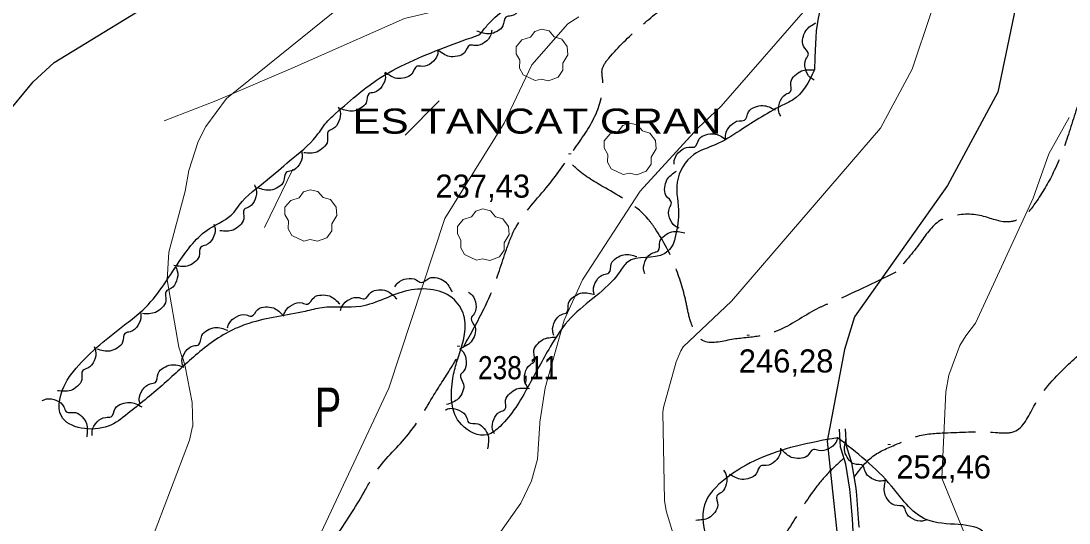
# Model space of a CAD drawing. Extents: x 480269 to 484877, y 4383588 to 4386804.
# Drawn here: x 483238.1 to 483634.3, y 4385540.7 to 4385730.7 of the extents above; entities that cross this region are included whole.
import ezdxf
from ezdxf.enums import TextEntityAlignment as Align

# ---------------------------------------------------------------- set-up
doc = ezdxf.new("R2010")
doc.units = 0
doc.header["$LTSCALE"] = 3.8
doc.linetypes.add('LONG_DASHED', pattern=[7.5, 6, -1.5])
doc.linetypes.add('MEDIUM_DASHED', pattern=[4.5, 3, -1.5])
for name, color, linetype, lineweight in [('27', 7, 'Continuous', 25), ('29', 7, 'Continuous', 13), ('38', 7, 'Continuous', 25), ('51', 7, 'Continuous', 13), ('7', 7, 'Continuous', 13), ('8', 7, 'Continuous', 25), ('9', 7, 'Continuous', 13)]:
    doc.layers.add(name, color=color, linetype=linetype, lineweight=lineweight)
doc.layers.add('31', color=7, linetype='Continuous')
doc.layers.add('5', color=7, linetype='Continuous')

msp = doc.modelspace()

# ---------------------------------------------------------------- linework, layer by layer
at = {"layer": '27'}
for points in [[(483411.62, 4385725.63), (483414.38, 4385729.12), (483445.75, 4385743.87), (483460.12, 4385746.17), (483467.72, 4385750.51), (483481.35, 4385756.24), (483494.17, 4385762.47), (483510.38, 4385771.95), (483513.98, 4385779.76), (483520.25, 4385796.38), (483532.76, 4385804.22), (483539.43, 4385807.59), (483542.56, 4385816.61), (483548.02, 4385830.65), (483556.04, 4385838.51), (483560.7, 4385820.62), (483568.17, 4385814.97), (483571.22, 4385796.89), (483575.67, 4385789), (483572.83, 4385770.57), (483560.28, 4385760.77), (483555.71, 4385755.51), (483541.6, 4385738.48), (483538.33, 4385719.63), (483538.1, 4385712.19)], [(483427.62, 4385740.1), (483427.84, 4385738.34), (483426.43, 4385734.81), (483423.43, 4385732.66), (483421.43, 4385732.22), (483420.27, 4385728.86), (483418.1, 4385726.81), (483415.23, 4385725.85), (483410.38, 4385726.92)], [(483537.98, 4385708.39), (483536.48, 4385709.34), (483534.64, 4385712.65), (483534.87, 4385716.34), (483535.79, 4385718.17), (483533.92, 4385721.19), (483533.71, 4385724.17), (483534.78, 4385727), (483538.66, 4385730.08)], [(483538.1, 4385712.19), (483529.76, 4385700.75), (483526.84, 4385699.24), (483509.81, 4385689.19), (483500.55, 4385683.88), (483492.53, 4385680.19), (483486.19, 4385669.67), (483486.71, 4385657.76), (483485.29, 4385648.37), (483485.16, 4385647.8), (483481.49, 4385642.76), (483467.34, 4385639.44), (483464.26, 4385635.56), (483446.1, 4385618.52), (483438.16, 4385607.39), (483429.82, 4385592.36), (483419.2, 4385577.29), (483414.42, 4385574.14), (483404.58, 4385577.96), (483401.38, 4385595.6), (483402.78, 4385601.5), (483405.77, 4385618.38), (483401.92, 4385625.2), (483384.54, 4385628.72), (483366.51, 4385622.71), (483351.92, 4385622.2), (483345.46, 4385620.82), (483324.28, 4385616.29), (483317.38, 4385613.48), (483303.26, 4385603.51), (483291.44, 4385592.81), (483278.46, 4385582.12), (483271.01, 4385577.36), (483253.33, 4385581.16), (483255.15, 4385594.09), (483258.92, 4385599.33), (483277.81, 4385616.18), (483284.13, 4385621.33), (483297.88, 4385639.66), (483309.29, 4385652.14), (483318.55, 4385658.26), (483320.55, 4385660.97), (483331.14, 4385670.55), (483339.59, 4385677.76), (483349.83, 4385687.26), (483354.13, 4385693), (483355.92, 4385694.7), (483364.88, 4385702.55), (483372.51, 4385708.31), (483398.18, 4385720.66), (483411.62, 4385725.63)], [(483416.08, 4385727.28), (483415.76, 4385725.53), (483413.38, 4385722.58), (483409.88, 4385721.4), (483407.83, 4385721.57), (483405.74, 4385718.7), (483403.06, 4385717.39), (483400.04, 4385717.32), (483395.72, 4385719.76)], [(483395.77, 4385719.65), (483395.53, 4385717.89), (483393.28, 4385714.84), (483389.83, 4385713.52), (483387.78, 4385713.6), (483385.81, 4385710.64), (483383.19, 4385709.22), (483380.17, 4385709.01), (483375.76, 4385711.27)], [(483375.57, 4385711.26), (483375.84, 4385709.51), (483374.54, 4385705.94), (483371.61, 4385703.7), (483369.62, 4385703.2), (483368.57, 4385699.8), (483366.45, 4385697.69), (483363.62, 4385696.64), (483358.74, 4385697.56)], [(483525.32, 4385694.66), (483524.62, 4385696.29), (483524.97, 4385700.07), (483527.23, 4385702.99), (483529.03, 4385703.98), (483529.18, 4385707.53), (483530.69, 4385710.11), (483533.17, 4385711.84), (483538.11, 4385712.19)], [(483358.03, 4385698.17), (483358.72, 4385696.54), (483358.31, 4385692.76), (483356, 4385689.88), (483354.19, 4385688.92), (483353.99, 4385685.37), (483352.44, 4385682.81), (483349.94, 4385681.12), (483344.99, 4385680.83)], [(483504.52, 4385686.07), (483504.51, 4385687.85), (483506.34, 4385691.17), (483509.57, 4385692.95), (483511.62, 4385693.14), (483513.17, 4385696.34), (483515.58, 4385698.11), (483518.54, 4385698.72), (483523.22, 4385697.08)], [(483485.02, 4385676.58), (483485.17, 4385678.35), (483487.27, 4385681.51), (483490.64, 4385683.01), (483492.7, 4385683.03), (483494.51, 4385686.09), (483497.06, 4385687.64), (483500.06, 4385688), (483504.59, 4385685.97)], [(483344.1, 4385681.61), (483344.41, 4385679.86), (483343.19, 4385676.27), (483340.31, 4385673.96), (483338.34, 4385673.41), (483337.36, 4385669.99), (483335.3, 4385667.84), (483332.49, 4385666.73), (483327.59, 4385667.53)], [(483603.65, 4385366.99), (483624.2, 4385382.47), (483632.03, 4385398.91), (483636.72, 4385422.41), (483645.34, 4385439.65), (483660.21, 4385444.35), (483671.96, 4385455.31), (483662.56, 4385467.06), (483659.43, 4385476.46), (483674.31, 4385492.91), (483694.66, 4385499.96), (483704.06, 4385490.56), (483711.11, 4385468.63), (483722.85, 4385451.4), (483736.16, 4385456.1), (483742.42, 4385467.85), (483748.69, 4385484.3), (483759.65, 4385490.56), (483776.88, 4385484.3), (483802.71, 4385469.41), (483826.99, 4385463.15), (483860.65, 4385463.15), (483873.96, 4385476.46), (483902.15, 4385486.65), (483911.55, 4385506.23), (483932.69, 4385513.28), (483942.86, 4385514.85), (483932.69, 4385531.3), (483915.46, 4385547.75), (483903.72, 4385547.75), (483886.49, 4385539.13), (483871.61, 4385529.73), (483863.78, 4385533.65), (483865.35, 4385544.61), (483871.61, 4385560.28), (483873.96, 4385572.03), (483874.75, 4385588.48), (483884.93, 4385596.31), (483910.76, 4385592.4), (483924.07, 4385597.1), (483936.6, 4385618.25), (483939.73, 4385664.46), (483945.7, 4385679.85)], [(483486.97, 4385652.28), (483485.4, 4385653.1), (483483.31, 4385656.27), (483483.24, 4385659.96), (483484.02, 4385661.86), (483481.92, 4385664.72), (483481.48, 4385667.67), (483482.32, 4385670.58), (483485.96, 4385673.95)], [(483326.32, 4385668.68), (483327.01, 4385667.04), (483326.61, 4385663.27), (483324.31, 4385660.38), (483322.5, 4385659.42), (483322.3, 4385655.87), (483320.76, 4385653.31), (483318.26, 4385651.61), (483313.31, 4385651.32)], [(483310.96, 4385653.88), (483311.44, 4385652.17), (483310.58, 4385648.47), (483307.94, 4385645.89), (483306.03, 4385645.15), (483305.39, 4385641.65), (483303.55, 4385639.31), (483300.86, 4385637.92), (483295.91, 4385638.24)], [(483473.96, 4385635.02), (483473.49, 4385636.74), (483474.37, 4385640.42), (483477.03, 4385642.99), (483478.95, 4385643.72), (483479.6, 4385647.21), (483481.46, 4385649.55), (483484.15, 4385650.92), (483489.1, 4385650.57)], [(483454.85, 4385627.06), (483454.49, 4385628.8), (483455.61, 4385632.43), (483458.42, 4385634.82), (483460.39, 4385635.42), (483461.26, 4385638.86), (483463.27, 4385641.08), (483466.05, 4385642.27), (483470.96, 4385641.6)], [(483296.42, 4385637.8), (483297.16, 4385636.19), (483296.89, 4385632.4), (483294.69, 4385629.44), (483292.92, 4385628.41), (483292.85, 4385624.85), (483291.4, 4385622.24), (483288.96, 4385620.45), (483284.02, 4385619.99)], [(483379.43, 4385630.1), (483380.46, 4385631.54), (483383.88, 4385633.19), (483387.54, 4385632.75), (483389.32, 4385631.72), (483392.44, 4385633.43), (483395.43, 4385633.46), (483398.19, 4385632.24), (483401.04, 4385628.18)], [(483337.4, 4385619.1), (483337.96, 4385620.78), (483340.74, 4385623.36), (483344.38, 4385624.02), (483346.38, 4385623.56), (483348.86, 4385626.11), (483351.7, 4385627.02), (483354.7, 4385626.66), (483358.62, 4385623.62)], [(483358.91, 4385621.14), (483359.48, 4385622.82), (483362.28, 4385625.38), (483365.92, 4385626.02), (483367.91, 4385625.54), (483370.41, 4385628.07), (483373.26, 4385628.97), (483376.26, 4385628.59), (483380.16, 4385625.53)], [(483407.24, 4385628.13), (483408.62, 4385627.02), (483410.05, 4385623.51), (483409.39, 4385619.87), (483408.26, 4385618.16), (483409.76, 4385614.94), (483409.62, 4385611.96), (483408.22, 4385609.28), (483404, 4385606.68)], [(483439.58, 4385611.67), (483439.1, 4385613.38), (483439.94, 4385617.08), (483442.56, 4385619.68), (483444.47, 4385620.42), (483445.09, 4385623.92), (483446.92, 4385626.28), (483449.6, 4385627.68), (483454.55, 4385627.38)], [(483316.19, 4385614.56), (483316.75, 4385616.24), (483319.53, 4385618.82), (483323.16, 4385619.49), (483325.17, 4385619.03), (483327.65, 4385621.57), (483330.49, 4385622.49), (483333.49, 4385622.13), (483337.41, 4385619.09)], [(483283.12, 4385620.81), (483283.44, 4385619.06), (483282.26, 4385615.46), (483279.41, 4385613.12), (483277.44, 4385612.55), (483276.5, 4385609.12), (483274.46, 4385606.94), (483271.66, 4385605.8), (483266.75, 4385606.55)], [(483299.18, 4385600.32), (483298.94, 4385602.08), (483300.32, 4385605.61), (483303.29, 4385607.8), (483305.29, 4385608.26), (483306.41, 4385611.64), (483308.56, 4385613.7), (483311.42, 4385614.69), (483316.28, 4385613.68)], [(483429.63, 4385592.15), (483428.74, 4385593.68), (483428.64, 4385597.48), (483430.54, 4385600.64), (483432.2, 4385601.84), (483431.93, 4385605.39), (483433.12, 4385608.13), (483435.37, 4385610.14), (483440.24, 4385611.08)], [(483265.69, 4385607.57), (483266.3, 4385605.9), (483265.73, 4385602.15), (483263.3, 4385599.37), (483261.45, 4385598.49), (483261.09, 4385594.95), (483259.44, 4385592.47), (483256.87, 4385590.88), (483251.91, 4385590.81)], [(483403.99, 4385606.68), (483405.27, 4385605.46), (483406.41, 4385601.84), (483405.46, 4385598.27), (483404.19, 4385596.66), (483405.43, 4385593.33), (483405.04, 4385590.37), (483403.43, 4385587.81), (483399.01, 4385585.56)], [(483283.06, 4385585.79), (483282.77, 4385587.54), (483284.02, 4385591.12), (483286.92, 4385593.41), (483288.91, 4385593.93), (483289.91, 4385597.35), (483291.99, 4385599.48), (483294.81, 4385600.57), (483299.7, 4385599.72)], [(483417.05, 4385574.52), (483416.39, 4385576.17), (483416.86, 4385579.94), (483419.22, 4385582.78), (483421.05, 4385583.72), (483421.31, 4385587.26), (483422.9, 4385589.79), (483425.43, 4385591.45), (483430.38, 4385591.64)], [(483246.07, 4385587.04), (483247.73, 4385587.67), (483251.49, 4385587.12), (483254.28, 4385584.71), (483255.18, 4385582.86), (483258.72, 4385582.53), (483261.22, 4385580.89), (483262.82, 4385578.33), (483262.92, 4385573.37)], [(483264.98, 4385573.89), (483265, 4385575.67), (483266.86, 4385578.97), (483270.11, 4385580.72), (483272.16, 4385580.89), (483273.74, 4385584.08), (483276.16, 4385585.82), (483279.13, 4385586.4), (483283.8, 4385584.71)], [(483398.51, 4385583.59), (483400.21, 4385584.1), (483403.92, 4385583.31), (483406.55, 4385580.72), (483407.32, 4385578.81), (483410.83, 4385578.25), (483413.21, 4385576.45), (483414.65, 4385573.78), (483414.42, 4385568.83)], [(483546.8, 4385573.01), (483530.82, 4385569.72), (483504.5, 4385557.5), (483496.51, 4385547.62), (483497.92, 4385533.98), (483509.2, 4385521.29), (483517.19, 4385516.59), (483525.65, 4385519.41), (483535.05, 4385523.64), (483540.22, 4385520.82), (483543.04, 4385508.12), (483538.34, 4385488.84), (483519.07, 4385474.27), (483501.68, 4385462.04), (483485.7, 4385448.88), (483481.94, 4385449.35), (483483.82, 4385456.4), (483491.34, 4385463.45), (483493.69, 4385472.39), (483482.41, 4385488.84), (483469.72, 4385479.44), (483457.5, 4385473.8), (483447.16, 4385476.15), (483435.41, 4385469.57), (483432.12, 4385452.64), (483431.65, 4385426.31), (483427.89, 4385415.96), (483416.61, 4385410.32), (483407.68, 4385404.21), (483394.53, 4385402.8), (483381.37, 4385399.03), (483373.85, 4385390.57), (483366.33, 4385379.29), (483360.69, 4385372.7), (483348.47, 4385369.41), (483324.97, 4385367.06), (483298.65, 4385356.72), (483277.03, 4385345.43), (483258.23, 4385329.91), (483253.06, 4385332.26), (483259.17, 4385339.32), (483268.1, 4385347.78), (483265.28, 4385357.19), (483251.65, 4385366.59), (483243.66, 4385376.46), (483231.44, 4385369.41), (483229.09, 4385383.05), (483230.97, 4385390.1)], [(483546.8, 4385573.01), (483546.23, 4385571.33), (483543.43, 4385568.77), (483539.79, 4385568.14), (483537.79, 4385568.61), (483535.29, 4385566.09), (483532.44, 4385565.19), (483529.44, 4385565.58), (483525.54, 4385568.64)], [(483677.76, 4385562.31), (483673.47, 4385559.38), (483664.07, 4385546.21), (483641.98, 4385535.4), (483622.71, 4385528.34), (483605.79, 4385512.83), (483595.92, 4385502.95), (483584.17, 4385505.77), (483587.93, 4385512.36), (483602.97, 4385527.4), (483602.97, 4385535.87), (483581.82, 4385541.51), (483567.25, 4385554.67), (483546.8, 4385573.01)], [(483565.04, 4385557), (483563.31, 4385556.59), (483559.66, 4385557.62), (483557.2, 4385560.37), (483556.54, 4385562.32), (483553.08, 4385563.1), (483550.81, 4385565.05), (483549.55, 4385567.8), (483550.09, 4385572.73)], [(483525.28, 4385569.1), (483525.18, 4385567.33), (483523.18, 4385564.11), (483519.85, 4385562.51), (483517.8, 4385562.42), (483516.08, 4385559.31), (483513.58, 4385557.68), (483510.59, 4385557.23), (483506.01, 4385559.13)], [(483503.69, 4385560.77), (483504.6, 4385559.24), (483504.74, 4385555.45), (483502.88, 4385552.27), (483501.22, 4385551.05), (483501.53, 4385547.51), (483500.37, 4385544.76), (483498.14, 4385542.72), (483493.28, 4385541.73)], [(483580.64, 4385541.92), (483578.94, 4385541.43), (483575.24, 4385542.28), (483572.64, 4385544.9), (483571.89, 4385546.81), (483568.39, 4385547.43), (483566.03, 4385549.26), (483564.64, 4385551.94), (483564.93, 4385556.89)]]:
    msp.add_spline(points, degree=3, dxfattribs=at)
at = {"layer": '29'}
for points in [[(483432.49, 4385708.2), (483427.95, 4385710.32), (483426.54, 4385712.86), (483426.64, 4385715.84), (483425.27, 4385718.25), (483425.31, 4385721), (483427.47, 4385723.6), (483430.66, 4385724.6), (483432.31, 4385726.79), (483434.88, 4385727.62), (483437.74, 4385726.97), (483439.69, 4385724.7), (483442.5, 4385723.88), (483444.63, 4385721.03), (483444.87, 4385717.9), (483442.99, 4385714.75), (483442.99, 4385712.07), (483441.17, 4385709.46), (483437.55, 4385708.12), (483434.78, 4385708.75)], [(483465.81, 4385672.62), (483461.27, 4385674.74), (483459.86, 4385677.28), (483459.96, 4385680.26), (483458.59, 4385682.67), (483458.63, 4385685.42), (483460.79, 4385688.02), (483463.98, 4385689.02), (483465.63, 4385691.21), (483468.2, 4385692.04), (483471.06, 4385691.39), (483473.01, 4385689.12), (483475.82, 4385688.3), (483477.95, 4385685.45), (483478.19, 4385682.32), (483476.31, 4385679.17), (483476.31, 4385676.49), (483474.49, 4385673.88), (483470.87, 4385672.54), (483468.1, 4385673.17)], [(483345.07, 4385647.43), (483340.53, 4385649.55), (483339.12, 4385652.09), (483339.22, 4385655.07), (483337.85, 4385657.48), (483337.89, 4385660.23), (483340.05, 4385662.83), (483343.24, 4385663.83), (483344.89, 4385666.02), (483347.46, 4385666.85), (483350.32, 4385666.2), (483352.27, 4385663.93), (483355.08, 4385663.11), (483357.21, 4385660.26), (483357.45, 4385657.13), (483355.57, 4385653.98), (483355.57, 4385651.3), (483353.75, 4385648.69), (483350.13, 4385647.35), (483347.36, 4385647.98)], [(483410.28, 4385640.17), (483405.74, 4385642.29), (483404.33, 4385644.83), (483404.43, 4385647.81), (483403.06, 4385650.22), (483403.1, 4385652.97), (483405.26, 4385655.57), (483408.45, 4385656.57), (483410.1, 4385658.76), (483412.67, 4385659.59), (483415.53, 4385658.94), (483417.48, 4385656.67), (483420.29, 4385655.85), (483422.42, 4385653), (483422.66, 4385649.87), (483420.78, 4385646.72), (483420.78, 4385644.04), (483418.96, 4385641.43), (483415.34, 4385640.09), (483412.57, 4385640.72)]]:
    msp.add_lwpolyline(points, close=True, dxfattribs=at)
at = {"layer": '38'}
msp.add_lwpolyline([(483552.77, 4385537.55), (483552.47, 4385542.27), (483551.73, 4385551.05), (483551.49, 4385553.6), (483549.9, 4385562.95), (483548.28, 4385568.32), (483547.92, 4385569.42), (483547.55, 4385576.23)], dxfattribs=at)
at = {"layer": '38', "linetype": 'MEDIUM_DASHED'}
msp.add_lwpolyline([(483561.28, 4385439.02), (483565.89, 4385449.17), (483567.14, 4385456.9), (483567.2, 4385464.1), (483567.16, 4385466.2), (483568.62, 4385474.3), (483569.47, 4385477.73), (483570.95, 4385483.54), (483570.94, 4385486.99), (483569.15, 4385493.62), (483565.29, 4385501.69), (483560.98, 4385507.84), (483559.66, 4385511.97), (483558.57, 4385516.81), (483557, 4385522.51), (483555.08, 4385539.19), (483554.99, 4385539.22), (483554.78, 4385542.44), (483554.04, 4385551.25), (483553.79, 4385553.9), (483552.16, 4385563.48), (483550.49, 4385569.01), (483550.22, 4385569.85), (483549.87, 4385576.35)], dxfattribs=at)
at = {"layer": '38', "linetype": 'LONG_DASHED'}
for points in [[(483222.84, 4385328.78), (483233.49, 4385331.65), (483248.44, 4385336.61), (483252.54, 4385340.94), (483258.88, 4385354.18), (483261.76, 4385364.09), (483264.07, 4385370.4), (483271.55, 4385381.16), (483280.42, 4385394.23), (483287.47, 4385408.23), (483295.91, 4385425.29), (483304.52, 4385439.96), (483308.91, 4385446.59), (483318.63, 4385460.51), (483325.16, 4385473.38), (483329.03, 4385484.99), (483336.9, 4385500.43), (483342.08, 4385509.3), (483351.29, 4385526.25), (483356.88, 4385535.07), (483367.82, 4385552.46), (483372.61, 4385560.56), (483384.55, 4385574.31), (483394.22, 4385589.19), (483401.11, 4385600.15), (483408.96, 4385613.82), (483416.11, 4385628.46), (483421.62, 4385644.25), (483425.26, 4385652.82), (483437.44, 4385668.5), (483447.61, 4385682.66), (483455.49, 4385695.61), (483457.94, 4385709.1), (483457.8, 4385712.22), (483460.32, 4385716.64), (483471.95, 4385728.32), (483483.41, 4385737.85), (483491.91, 4385744.84), (483502.88, 4385754.26), (483511.53, 4385762), (483517.86, 4385770.14), (483520.82, 4385773.68), (483521.2, 4385789.84), (483522.3, 4385808.2), (483521.83, 4385825.17), (483522.61, 4385837.11), (483524.33, 4385844.04), (483529.61, 4385862.88), (483530.12, 4385879.57), (483529.5, 4385895.4), (483531.44, 4385911.89), (483533.11, 4385922.24), (483534.94, 4385934.41), (483535.75, 4385947.11), (483535.49, 4385954.95), (483538.08, 4385971.48), (483542.8, 4385983), (483551.34, 4385997.49), (483555.36, 4386004.16), (483555.47, 4386004.25)], [(483804.51, 4385920.94), (483788.05, 4385895.48), (483779.36, 4385885.64), (483767.14, 4385873.56), (483740.9, 4385842.33), (483734.1, 4385833.64), (483725.43, 4385817.26), (483714.11, 4385791.82), (483710.8, 4385781.06), (483710.16, 4385770.49), (483707.13, 4385759.38), (483703.28, 4385752.81), (483694.46, 4385748.4), (483680.9, 4385745.07), (483669.5, 4385743.91), (483655.77, 4385731.07), (483647.05, 4385718.23), (483639.81, 4385704.57), (483634.39, 4385688.76), (483628.75, 4385674.1), (483622.15, 4385662.64), (483615.35, 4385655.69), (483611.37, 4385654.69), (483601.39, 4385656.95), (483588.98, 4385656.57), (483586.28, 4385655.56), (483578.11, 4385646.87), (483568.89, 4385635.65)], [(483269.19, 4385377.79), (483265.83, 4385379.76), (483259.03, 4385384.12), (483248.33, 4385390.08), (483241.93, 4385401.56), (483240.31, 4385411.32), (483239.53, 4385423.1), (483237.61, 4385429.2), (483228.77, 4385444.16), (483215.59, 4385471.64), (483211.39, 4385484.05), (483206.78, 4385496.53), (483203.95, 4385506.6), (483198.79, 4385527.78), (483197.64, 4385533.81), (483194.47, 4385554.66), (483187.12, 4385575.33), (483180.81, 4385599.81), (483178.92, 4385612.27), (483174.66, 4385634.07), (483172.09, 4385649.52), (483170.18, 4385665.56), (483170.94, 4385687.86), (483170.82, 4385701.87), (483170.52, 4385716.56), (483170.83, 4385718.14), (483172.28, 4385738.14), (483175.1, 4385763.48), (483174.2, 4385772.45), (483177.9, 4385781.99), (483183.14, 4385788.4), (483185.49, 4385797.11), (483184.14, 4385804.05), (483177.92, 4385810.59), (483174.55, 4385813.49), (483148.28, 4385826.01)], [(483553.1, 4385558.04), (483560, 4385565.85), (483569.77, 4385570.8), (483577.16, 4385573.63), (483588.52, 4385574.9), (483606.53, 4385575.01), (483613.6, 4385575.34), (483621.08, 4385584.92), (483634.19, 4385600.86), (483645.77, 4385609.97), (483659.79, 4385616.6), (483667.57, 4385620.28), (483678.63, 4385624.9), (483689.28, 4385631.34), (483694.37, 4385636.14), (483695.55, 4385637.52), (483703.2, 4385641.14), (483713.48, 4385650.23), (483722.91, 4385663.28), (483730.98, 4385671.49), (483737.59, 4385678.35), (483745.67, 4385681.84), (483752.15, 4385685.91), (483758.36, 4385690.52), (483768.54, 4385697.31), (483775.64, 4385697.41), (483781.1, 4385695.52), (483798.4, 4385686.78), (483802.9, 4385685.22), (483810.56, 4385679.57), (483815.98, 4385668.59), (483816.07, 4385663.36), (483817.61, 4385654.53), (483820.08, 4385648.86), (483825.53, 4385639.54), (483832.15, 4385630.46), (483841.58, 4385619.39), (483852.28, 4385607.67), (483862.9, 4385601.96)], [(483568.89, 4385635.65), (483543.81, 4385623.92), (483539.76, 4385622.12), (483525.04, 4385613.89), (483517.1, 4385611.47), (483506.82, 4385610.16), (483495.8, 4385609.84), (483491.23, 4385617.07), (483489.65, 4385623.74), (483485.64, 4385637.2), (483477.81, 4385652.24), (483475.21, 4385655.72), (483459.88, 4385667.02), (483448.76, 4385674.3), (483444.57, 4385678.38)], [(483549.18, 4385565.2), (483543.95, 4385560.32), (483538.38, 4385553.83), (483529.64, 4385540.66), (483519.21, 4385523.41), (483514.75, 4385515.06), (483505.58, 4385506.46), (483497.79, 4385499.89), (483493.59, 4385496.17), (483487.25, 4385486.55), (483482.3, 4385477.14), (483479.01, 4385472.04), (483472.56, 4385464.14), (483468.73, 4385461.99), (483458.51, 4385464.43), (483444.6, 4385463.08), (483435.34, 4385459.51), (483429.43, 4385458.44), (483416.58, 4385458.99), (483403.28, 4385460.76), (483384.88, 4385459.21), (483372.63, 4385454.93), (483365.84, 4385453.56), (483350.1, 4385452.09), (483330.85, 4385457.31), (483319.64, 4385462.11)]]:
    msp.add_spline(points, degree=3, dxfattribs=at)
at = {"layer": '51'}
for p, q in [((483396.17, 4385700.52), (483383.37, 4385687.5)), ((483330.18, 4385652.54), (483340.82, 4385674.67))]:
    msp.add_line(p, q, dxfattribs=at)
msp.add_lwpolyline([(483518.19, 4385778.58), (483483.09, 4385760.05), (483458.37, 4385749.62), (483427.91, 4385742.41), (483383.06, 4385731.68), (483341.78, 4385713.39), (483311.74, 4385700.46), (483292.21, 4385692.99)], dxfattribs=at)
at = {"layer": '7'}
for p, q in [((483445.13, 4385680.42), (483446.13, 4385680.42)), ((483512.51, 4385611.84), (483513.51, 4385611.84)), ((483403, 4385607.67), (483404, 4385607.67)), ((483565.87, 4385570.39), (483566.87, 4385570.39))]:
    msp.add_line(p, q, dxfattribs=at)
at = {"layer": '8'}
for points in [[(483753.34, 4386095.07), (483741.77, 4386077.52), (483729.02, 4386044.1), (483719.89, 4385998.13), (483700.85, 4385936.57), (483673.49, 4385898.65), (483634.96, 4385827.01), (483619.32, 4385779.29), (483617.06, 4385750.43), (483607.42, 4385703.77), (483588.4, 4385668.48), (483553.23, 4385618.74), (483549.49, 4385606.42), (483542.9, 4385571.76), (483548.23, 4385522.15)], [(483231.52, 4385694.08), (483242.69, 4385707.73), (483250.64, 4385715.03), (483295.58, 4385742.7)]]:
    msp.add_lwpolyline(points, dxfattribs=at)
at = {"layer": '9'}
for points in [[(483727.12, 4386131.2), (483661.13, 4386034.7), (483651.03, 4386022.71), (483628.43, 4385968.79), (483624.88, 4385961.8), (483576.94, 4385892.18), (483574.11, 4385886.87), (483560.9, 4385844.83), (483549.36, 4385779.3), (483534.38, 4385734.95), (483533.77, 4385734.08), (483502.81, 4385698.5), (483494.02, 4385690.15), (483472.18, 4385666.38), (483450.35, 4385632.8), (483443.48, 4385617.49), (483436.28, 4385591.84), (483434.25, 4385578.86), (483434.26, 4385578.33)], [(483277.8, 4385508.95), (483301.8, 4385572.04), (483302.98, 4385577.3), (483302.98, 4385577.31), (483302.99, 4385577.32), (483302.77, 4385586.31), (483300.2, 4385600), (483299.35, 4385602.79), (483299.17, 4385602.99), (483297.81, 4385607.33), (483293.4, 4385632.71), (483294.02, 4385643.24), (483300.14, 4385666.37), (483301.52, 4385674.11), (483305.03, 4385685.18), (483308, 4385690.8), (483315.79, 4385701.38), (483360.64, 4385737.64)], [(483484.54, 4385536.97), (483482.02, 4385545.37), (483481.37, 4385549.22), (483480.78, 4385582.65), (483481.05, 4385584.44), (483485.85, 4385601.7), (483487.56, 4385605.94), (483488.42, 4385607.36), (483506.71, 4385624.74), (483563.08, 4385690.14), (483574.97, 4385712.44), (483582.18, 4385733.89)], [(483348.65, 4385530.95), (483377.1, 4385591.73), (483398.29, 4385655.97), (483420.81, 4385692.06), (483431.23, 4385714.11), (483444.87, 4385729.62), (483448.96, 4385732.35)], [(483646.34, 4385468.94), (483629.82, 4385485.21), (483623.22, 4385489.98), (483622.38, 4385490.7), (483621.03, 4385492.24), (483613.24, 4385504.08), (483601.37, 4385520.76), (483586.25, 4385557.67), (483587.76, 4385590.43), (483588.94, 4385596.69), (483593.08, 4385607.94), (483595.34, 4385611.54), (483598.94, 4385616.42), (483620.79, 4385663.69), (483626.74, 4385680.5), (483634.36, 4385694.19)], [(483434.26, 4385578.33), (483433.32, 4385564.94), (483431.09, 4385556.74), (483427.1, 4385548.19), (483403.47, 4385514.79)]]:
    msp.add_lwpolyline(points, dxfattribs=at)

# ---------------------------------------------------------------- texts
at = {"layer": '31', "width": 0.75}
msp.add_text('P', height=15, dxfattribs=at).set_placement((483354.16, 4385577.01), align=Align.CENTER)
at = {"layer": '5', "width": 1.25}
msp.add_text('ES TANCAT GRAN', height=9.5, dxfattribs=at).set_placement((483363.45, 4385688.09))
at = {"layer": '7'}
for s, p in [('237,43', (483394.76, 4385663.86)), ('246,28', (483509.46, 4385597.69)), ('252,46', (483569.03, 4385557.57))]:
    msp.add_text(s, height=8.75, dxfattribs=at).set_placement(p)
at = {"layer": '7', "width": 0.85}
msp.add_text('238,11', height=8.75, dxfattribs=at).set_placement((483410.84, 4385595.14))

doc.saveas('drawing.dxf')
